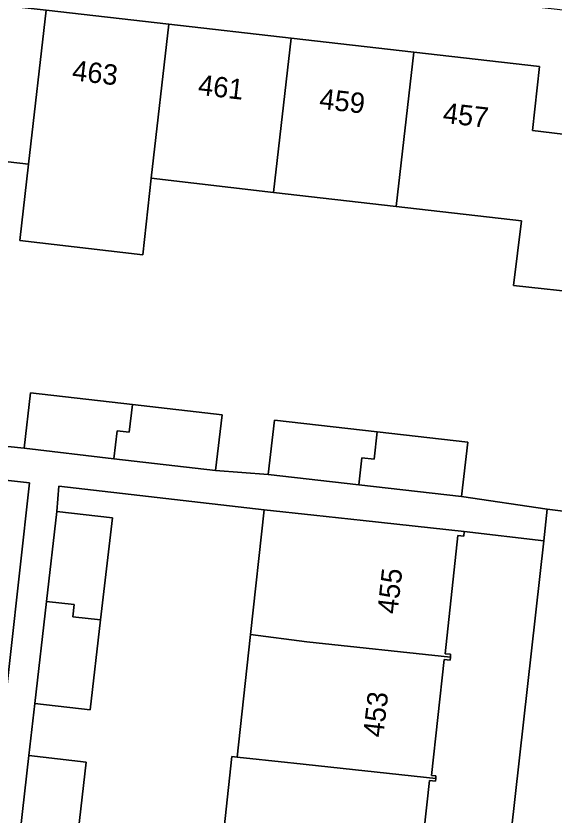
# Model space of a CAD drawing. Extents: x 161928 to 163071, y 386474 to 387428.
# Drawn here: x 162063.65 to 162090.1, y 387000.83 to 387040.09 of the extents above; entities that cross this region are included whole.
import ezdxf

# ---------------------------------------------------------------- set-up
doc = ezdxf.new("R2010")
doc.units = 0
for name, color, linetype in [('IMGEO_Erf', 7, 'Continuous'), ('IMGEO_Pand', 7, 'Continuous'), ('IMGEO_Pand_nummerreeks', 7, 'Continuous'), ('IMGEO_Rijbaan_lokaal_open', 7, 'Continuous'), ('IMGEO_Voetpad_open', 7, 'Continuous')]:
    doc.layers.add(name, color=color, linetype=linetype)

msp = doc.modelspace()

# ---------------------------------------------------------------- linework, layer by layer
at = {"layer": 'IMGEO_Erf'}
for points in [[(162092.941, 387040.089), (162090.107, 387040.42), (162053.258, 387044.538), (162053.273, 387044.667), (162053.232, 387044.673), (162052.938, 387041.772), (162059.112, 387041.065), (162065.136, 387040.375), (162071.16, 387039.686), (162077.183, 387038.996), (162083.207, 387038.307), (162089.378, 387037.6), (162089.04, 387034.471), (162092.569, 387034.041), (162091.726, 387026.452), (162088.106, 387026.85), (162088.494, 387030.02)], [(162061.319, 387019.135), (162064.056, 387018.849), (162064.371, 387021.579), (162069.373, 387021.003), (162073.778, 387020.496), (162073.463, 387017.765), (162076.053, 387017.561), (162076.359, 387020.238), (162081.406, 387019.661), (162085.855, 387019.152), (162085.549, 387016.475), (162089.765, 387015.862), (162091.874, 387015.603), (162091.89, 387015.75), (162092.186, 387018.428), (162092.97, 387025.536), (162094.369, 387037.059)], [(162088.494, 387030.02), (162082.34, 387030.729), (162076.317, 387031.423), (162070.294, 387032.117), (162069.881, 387028.361), (162063.841, 387029.051), (162064.271, 387032.811), (162058.247, 387033.505)], [(162073.604, 386997.613), (162074.26, 387003.707), (162074.529, 387003.678), (162075.164, 387009.548), (162075.182, 387009.711), (162075.844, 387015.83), (162065.756, 387016.989), (162065.663, 387015.752), (162068.391, 387015.438), (162067.813, 387010.42), (162067.303, 387005.999), (162064.575, 387006.313), (162064.289, 387003.758), (162067.103, 387003.434), (162066.714, 387000)], [(162087.995, 387000), (162089.592, 387014.308), (162085.686, 387014.764), (162085.661, 387014.53), (162085.376, 387014.56), (162084.748, 387008.759), (162085.016, 387008.73), (162085.001, 387008.588), (162084.986, 387008.446), (162084.696, 387008.477), (162084.079, 387002.773), (162084.291, 387002.759), (162084.283, 387002.63), (162084.275, 387002.498), (162083.978, 387002.53), (162083.704, 387000)]]:
    msp.add_lwpolyline(points, dxfattribs=at)
at = {"layer": 'IMGEO_Pand'}
for points in [[(162058.247, 387033.505), (162064.271, 387032.811), (162065.136, 387040.375), (162059.112, 387041.065)], [(162063.841, 387029.051), (162069.881, 387028.361), (162070.294, 387032.117), (162071.16, 387039.686), (162065.136, 387040.375), (162064.271, 387032.811)], [(162077.183, 387038.996), (162071.16, 387039.686), (162070.294, 387032.117), (162076.317, 387031.423)], [(162076.317, 387031.423), (162082.34, 387030.729), (162083.207, 387038.307), (162077.183, 387038.996)], [(162082.34, 387030.729), (162088.494, 387030.02), (162088.106, 387026.85), (162091.726, 387026.452), (162092.569, 387034.041), (162089.04, 387034.471), (162089.378, 387037.6), (162083.207, 387038.307)], [(162068.619, 387019.707), (162069.216, 387019.638), (162069.373, 387021.003), (162064.371, 387021.579), (162064.056, 387018.849), (162068.461, 387018.341)], [(162068.461, 387018.341), (162073.463, 387017.765), (162073.778, 387020.496), (162069.373, 387021.003), (162069.216, 387019.638), (162068.619, 387019.707)], [(162080.656, 387018.389), (162081.253, 387018.321), (162081.406, 387019.661), (162076.359, 387020.238), (162076.053, 387017.561), (162080.503, 387017.052)], [(162080.503, 387017.052), (162085.549, 387016.475), (162085.855, 387019.152), (162081.406, 387019.661), (162081.253, 387018.321), (162080.656, 387018.389)], [(162065.153, 387011.33), (162066.52, 387011.173), (162066.451, 387010.576), (162067.813, 387010.42), (162068.391, 387015.438), (162065.663, 387015.752)], [(162085.376, 387014.56), (162085.661, 387014.53), (162085.686, 387014.764), (162080.716, 387015.302), (162078.298, 387015.564), (162075.844, 387015.83), (162075.182, 387009.711), (162077.942, 387009.348), (162085.001, 387008.588), (162085.016, 387008.73), (162084.748, 387008.759)], [(162064.575, 387006.313), (162067.303, 387005.999), (162067.813, 387010.42), (162066.451, 387010.576), (162066.52, 387011.173), (162065.153, 387011.33)], [(162084.696, 387008.477), (162084.986, 387008.446), (162085.001, 387008.588), (162077.942, 387009.348), (162075.182, 387009.711), (162075.164, 387009.548), (162074.529, 387003.678), (162076.989, 387003.414), (162077.313, 387003.379), (162084.283, 387002.63), (162084.291, 387002.759), (162084.079, 387002.773)], [(162063.865, 387000), (162063.798, 386999.403), (162065.204, 386999.244), (162065.136, 386998.647), (162066.543, 386998.487), (162066.714, 387000), (162067.103, 387003.434), (162064.289, 387003.758)], [(162083.704, 387000), (162083.978, 387002.53), (162084.275, 387002.498), (162084.283, 387002.63), (162077.313, 387003.379), (162076.989, 387003.414), (162074.529, 387003.678), (162074.26, 387003.707), (162073.604, 386997.613), (162073.925, 386997.579), (162076.287, 386997.325), (162076.631, 386997.288), (162083.629, 386996.535), (162083.645, 386996.679), (162083.308, 386996.699)]]:
    msp.add_lwpolyline(points, close=True, dxfattribs=at)
at = {"layer": 'IMGEO_Rijbaan_lokaal_open'}
msp.add_lwpolyline([(162062.393, 387000), (162064.316, 387017.15), (162056.916, 387017.976), (162056.569, 387014.837), (162056.222, 387011.697), (162055.875, 387008.558), (162055.529, 387005.418), (162055.182, 387002.279), (162054.93, 387000), (162054.835, 386999.14), (162054.488, 386996), (162054.141, 386992.861), (162053.794, 386989.722), (162053.448, 386986.582), (162053.101, 386983.443), (162052.754, 386980.303), (162052.407, 386977.164), (162064.122, 386975.837), (162082.461, 386973.766), (162084.103, 386973.567), (162084.434, 386976.577), (162082.773, 386976.758), (162064.316, 386978.849), (162063.064, 386978.976)], dxfattribs=at)
at = {"layer": 'IMGEO_Voetpad_open'}
for points in [[(162094.369, 387037.059), (162092.97, 387025.536), (162092.186, 387018.428), (162091.89, 387015.75), (162091.874, 387015.603), (162089.765, 387015.862), (162089.592, 387014.308), (162087.995, 387000), (162085.531, 386977.917), (162085.474, 386976.471), (162085.131, 386973.429), (162084.831, 386972.042), (162086.478, 386971.871), (162086.726, 386971.082), (162086.749, 386970.255), (162084.594, 386949.273)], [(162063.865, 387000), (162064.289, 387003.758), (162064.575, 387006.313), (162065.153, 387011.33), (162065.663, 387015.752), (162065.756, 387016.989), (162075.844, 387015.83), (162078.298, 387015.564), (162080.716, 387015.302), (162085.686, 387014.764), (162089.592, 387014.308), (162089.765, 387015.862), (162085.549, 387016.475), (162080.503, 387017.052), (162076.053, 387017.561), (162073.463, 387017.765), (162068.461, 387018.341), (162064.056, 387018.849), (162061.319, 387019.135), (162056.293, 387019.714), (162056.092, 387018.077), (162056.916, 387017.976), (162064.316, 387017.15), (162062.393, 387000)]]:
    msp.add_lwpolyline(points, dxfattribs=at)

# ---------------------------------------------------------------- texts
at = {"layer": 'IMGEO_Pand_nummerreeks'}
for s, rotation, p in [('463', 353.4687, (162066.379, 387036.931)), ('461', 353.4687, (162072.565, 387036.224)), ('459', 353.4687, (162078.526, 387035.541)), ('457', 353.4687, (162084.599, 387034.845)), ('455', 83.4628, (162082.394, 387010.68)), ('453', 83.4628, (162081.699, 387004.616))]:
    msp.add_text(s, height=1, rotation=rotation, dxfattribs=at).set_placement(p)

doc.saveas('drawing.dxf')
